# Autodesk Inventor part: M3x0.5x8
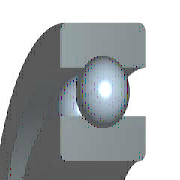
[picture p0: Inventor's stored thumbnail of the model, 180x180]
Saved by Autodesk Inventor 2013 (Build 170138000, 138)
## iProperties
Created: 2009-02
Part Number: M3x0.5x8
Material: 강, 연강
Description: 깊은 그루브 볼 베어링
Document SubType Name: Modeling
Standard: KS B 2023
Designer: KYOUNG IL JANG
Standards Organization: KS
Language: ko-KR
Size Designation: 6201 - 12 x 32 x 10
Categories: <MemberInstance><Categories><Category DisplayName="샤프트 부품" InternalName="7f7aeb1f-a693-4053-b835-cee3144e0d98" Mnemonic="SHFT"><Category DisplayName="베어링" Inter
Density: 7.86 g/cm^3
Mass: 36.8026 g
Surface Area: 42.5728 cm^2
Volume: 4.68226 cm^3
Vendor: CBT Solutions
Company: 한국ATC센터
IsCustomPart: 1
Author: KYOUNG IL JANG
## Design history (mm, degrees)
sketch "스케치" dims "d0" = 5.2 (= -0.26 x WD + 0.26 x BD)
  geometry: L1 (2.4, 11)-(7.6, 11); L2 (5, 11)-(5, 8.4); L3 (5, 11)-(5, 13.6); L4 (3.068, 9.26)-(0, 9.26); L5 (0, 6)-(10, 6); L6 (3.068, 12.74)-(0, 12.74); L7 (0, 16)-(10, 16); L8 (10, 6)-(10, 9.26); L9 (6.932, 9.26)-(10, 9.26); L10 (6.932, 12.74)-(10, 12.74); L11 (10, 16)-(10, 12.74); L12 (-1.4, 0)-(8.4, 0) reference; L13 (0, -0.3)-(0, 5.3) reference
  constraints: 22 end point, 4 point on line, 2 collinear, 2 perpendicular, 2 symmetric about line, 1 midpoint, 1 parallel, 14 other
  dimensions: "d9" = 12 diameter of L5 L12 (= WD); "d11" = 32 diameter of L7 L12 (= BD); "d12" = 10 distance between parallel lines of L8 L13 (= KB); "d13" = 18.52 diameter of L9 L12 (= 0.326 x BD + 0.674 x WD)
revolve "본체" stored, may be unused: angle "d6" = 90 deg
revolve "볼" stored, may be unused: angle "d7" = 90 deg
pattern_circular "IDS_ARRAYBALL[SIMPL:T]" dims angle "d3" = 360 deg
body "Solid1"
fillet "모깎기1" dims "d1" = 0.6 (= KRS)
other parameters: "WD" = 12 [user parameter; used in 5 equation terms], "BD" = 32 [user parameter; used in 5 equation terms], "KB" = 10 [user parameter; used in 1 equation term], "KRS" = 0.6 [user parameter; used in 1 equation term], "d4" = 0, "d5" = 0, "d8" = 0, "d14" = 0, "d15" = 0, "BBA" = 0 [user parameter], "BC0" = 3100000 [user parameter], "BC" = 6890000 [user parameter], "BR" = 16 (= 0.5 x BD) [user parameter], "WR" = 6 (= 0.5 x WD) [user parameter]
